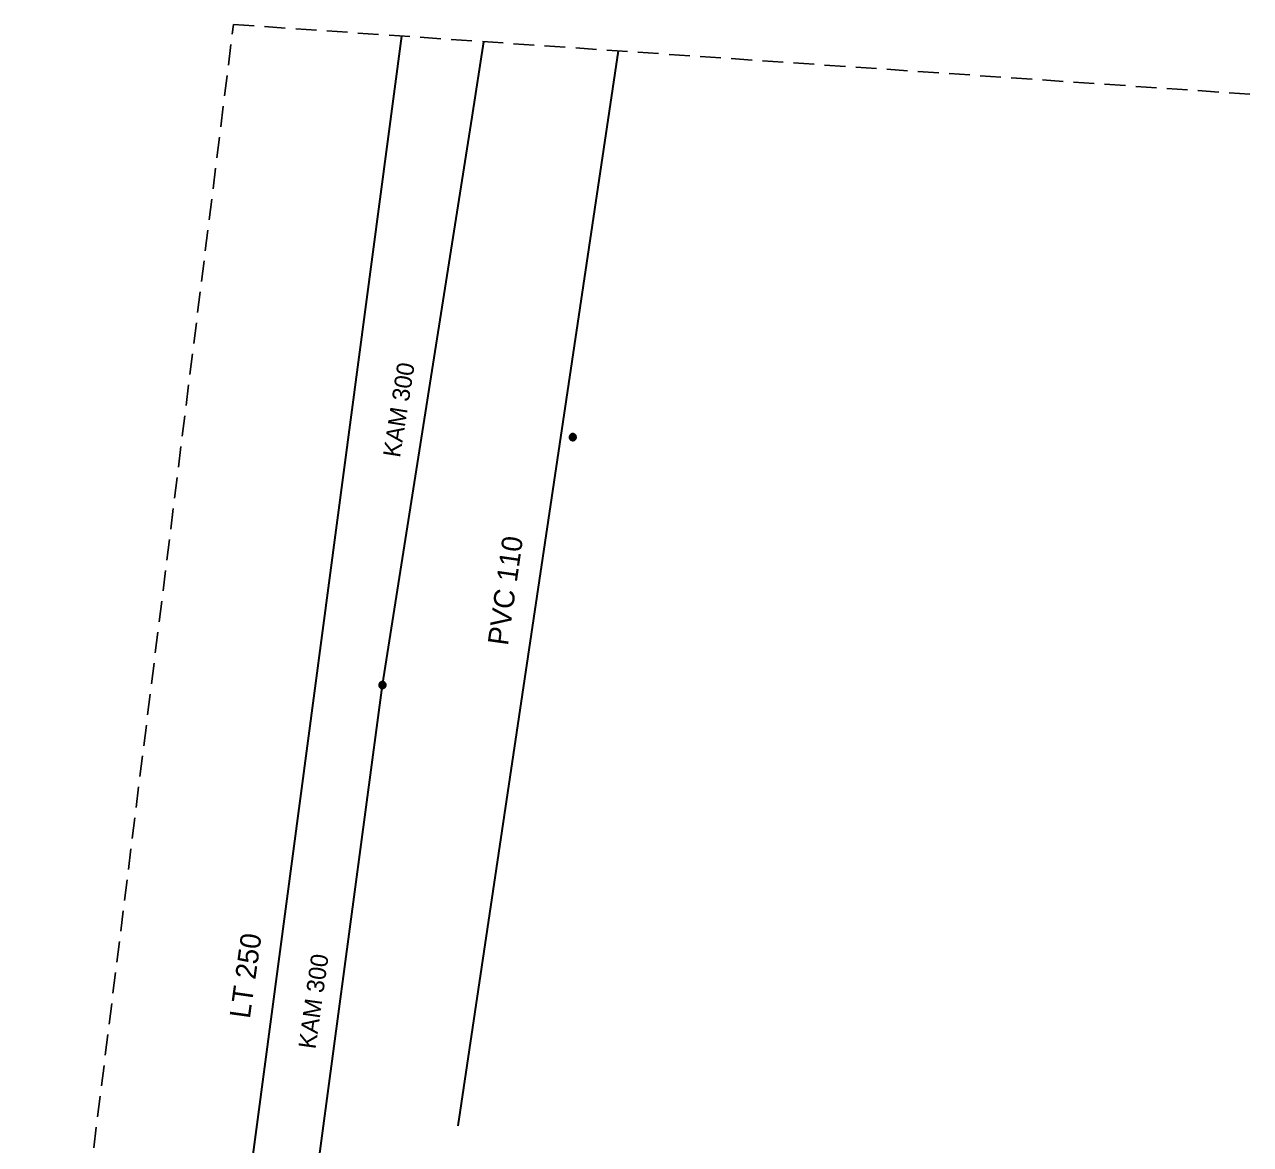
# Model space of a CAD drawing. Extents: x -866761 to -866592, y -1013996 to -1013877.
# Drawn here: x -866760.6 to -866682.7, y -1013947.7 to -1013876.6 of the extents above; entities that cross this region are included whole.
import ezdxf

# ---------------------------------------------------------------- set-up
doc = ezdxf.new("R2010")
doc.units = 0
doc.header["$LTSCALE"] = 0.44
doc.linetypes.add('MEDIUM_DASHED', pattern=[4.5, 3, -1.5])
for name, color, linetype, lineweight in [('1', 7, 'Continuous', 35), ('21', 7, 'Continuous', 35), ('32', 7, 'Continuous', 13), ('62', 7, 'MEDIUM_DASHED', 25), ('8', 7, 'Continuous', 13)]:
    doc.layers.add(name, color=color, linetype=linetype, lineweight=lineweight)

msp = doc.modelspace()

# ---------------------------------------------------------------- linework, layer by layer
at = {"layer": '1'}
msp.add_line((-866722.9, -1013878.242), (-866733.064, -1013946.511), dxfattribs=at)
msp.add_lwpolyline([(-866751.412, -1013984.065), (-866747.177, -1013956.779), (-866736.629, -1013877.301)], dxfattribs=at)
at = {"layer": '21'}
msp.add_line((-866743.067, -1013957.51), (-866737.854, -1013918.522), dxfattribs=at)
msp.add_lwpolyline([(-866737.854, -1013918.522), (-866732.171, -1013882.458), (-866731.425, -1013877.658)], dxfattribs=at)
at = {"layer": '32'}
for points in [[(-866737.623, -1013918.522), (-866737.629, -1013918.47), (-866737.646, -1013918.42), (-866737.675, -1013918.376), (-866737.712, -1013918.339), (-866737.757, -1013918.312), (-866737.807, -1013918.295), (-866737.86, -1013918.291), (-866737.912, -1013918.298), (-866737.961, -1013918.317), (-866738.004, -1013918.346), (-866738.04, -1013918.385), (-866738.066, -1013918.43), (-866738.082, -1013918.481), (-866738.085, -1013918.533), (-866738.077, -1013918.585), (-866738.057, -1013918.634), (-866738.026, -1013918.677), (-866737.987, -1013918.711), (-866737.941, -1013918.737), (-866737.89, -1013918.751), (-866737.837, -1013918.753), (-866737.786, -1013918.743), (-866737.738, -1013918.722), (-866737.695, -1013918.691), (-866737.661, -1013918.65), (-866737.637, -1013918.604), (-866737.625, -1013918.553)], [(-866737.653, -1013918.522), (-866737.659, -1013918.473), (-866737.676, -1013918.427), (-866737.704, -1013918.387), (-866737.741, -1013918.355), (-866737.785, -1013918.333), (-866737.833, -1013918.322), (-866737.882, -1013918.322), (-866737.929, -1013918.335), (-866737.972, -1013918.359), (-866738.008, -1013918.392), (-866738.035, -1013918.433), (-866738.051, -1013918.48), (-866738.055, -1013918.529), (-866738.048, -1013918.577), (-866738.029, -1013918.622), (-866737.999, -1013918.662), (-866737.961, -1013918.693), (-866737.917, -1013918.713), (-866737.869, -1013918.723), (-866737.82, -1013918.721), (-866737.773, -1013918.706), (-866737.73, -1013918.681), (-866737.696, -1013918.647), (-866737.67, -1013918.605), (-866737.656, -1013918.558)], [(-866737.683, -1013918.522), (-866737.689, -1013918.477), (-866737.706, -1013918.435), (-866737.734, -1013918.4), (-866737.77, -1013918.373), (-866737.812, -1013918.356), (-866737.857, -1013918.351), (-866737.902, -1013918.357), (-866737.943, -1013918.376), (-866737.978, -1013918.404), (-866738.005, -1013918.441), (-866738.021, -1013918.483), (-866738.025, -1013918.528), (-866738.018, -1013918.573), (-866737.999, -1013918.614), (-866737.97, -1013918.648), (-866737.933, -1013918.674), (-866737.89, -1013918.69), (-866737.845, -1013918.693), (-866737.8, -1013918.685), (-866737.76, -1013918.665), (-866737.726, -1013918.636), (-866737.7, -1013918.598), (-866737.686, -1013918.555)], [(-866737.713, -1013918.522), (-866737.718, -1013918.481), (-866737.736, -1013918.444), (-866737.763, -1013918.413), (-866737.798, -1013918.392), (-866737.838, -1013918.381), (-866737.879, -1013918.383), (-866737.918, -1013918.396), (-866737.952, -1013918.42), (-866737.977, -1013918.452), (-866737.992, -1013918.49), (-866737.995, -1013918.531), (-866737.987, -1013918.571), (-866737.967, -1013918.607), (-866737.938, -1013918.636), (-866737.901, -1013918.655), (-866737.861, -1013918.663), (-866737.82, -1013918.659), (-866737.782, -1013918.644), (-866737.75, -1013918.618), (-866737.727, -1013918.584), (-866737.714, -1013918.545)], [(-866737.743, -1013918.522), (-866737.748, -1013918.486), (-866737.766, -1013918.454), (-866737.792, -1013918.429), (-866737.826, -1013918.414), (-866737.862, -1013918.411), (-866737.897, -1013918.419), (-866737.928, -1013918.439), (-866737.951, -1013918.467), (-866737.964, -1013918.501), (-866737.964, -1013918.538), (-866737.953, -1013918.573), (-866737.932, -1013918.602), (-866737.902, -1013918.623), (-866737.867, -1013918.633), (-866737.83, -1013918.631), (-866737.796, -1013918.617), (-866737.769, -1013918.594), (-866737.75, -1013918.562), (-866737.743, -1013918.527)], [(-866737.773, -1013918.522), (-866737.778, -1013918.491), (-866737.795, -1013918.465), (-866737.821, -1013918.448), (-866737.851, -1013918.441), (-866737.882, -1013918.445), (-866737.909, -1013918.462), (-866737.927, -1013918.486), (-866737.935, -1013918.517), (-866737.931, -1013918.547), (-866737.916, -1013918.575), (-866737.892, -1013918.594), (-866737.862, -1013918.603), (-866737.831, -1013918.6), (-866737.803, -1013918.586), (-866737.783, -1013918.562), (-866737.773, -1013918.533)], [(-866737.803, -1013918.522), (-866737.808, -1013918.498), (-866737.825, -1013918.48), (-866737.848, -1013918.471), (-866737.872, -1013918.474), (-866737.893, -1013918.488), (-866737.904, -1013918.51), (-866737.904, -1013918.535), (-866737.892, -1013918.556), (-866737.872, -1013918.57), (-866737.847, -1013918.573), (-866737.824, -1013918.564), (-866737.808, -1013918.546)], [(-866737.833, -1013918.522), (-866737.838, -1013918.507), (-866737.853, -1013918.501), (-866737.868, -1013918.505), (-866737.875, -1013918.519), (-866737.871, -1013918.534), (-866737.858, -1013918.543), (-866737.843, -1013918.54), (-866737.833, -1013918.528)]]:
    msp.add_lwpolyline(points, close=True, dxfattribs=at)
at = {"layer": '62'}
msp.add_lwpolyline([(-866747.317, -1013876.568), (-866591.969, -1013887.219), (-866617.09, -1013995.541), (-866760.581, -1013983.282)], close=True, dxfattribs=at)
at = {"layer": '8'}
for points in [[(-866725.544, -1013902.778), (-866725.55, -1013902.726), (-866725.567, -1013902.676), (-866725.596, -1013902.632), (-866725.633, -1013902.595), (-866725.678, -1013902.568), (-866725.728, -1013902.551), (-866725.781, -1013902.547), (-866725.833, -1013902.554), (-866725.882, -1013902.573), (-866725.925, -1013902.602), (-866725.961, -1013902.641), (-866725.987, -1013902.686), (-866726.003, -1013902.737), (-866726.006, -1013902.789), (-866725.998, -1013902.841), (-866725.978, -1013902.89), (-866725.947, -1013902.933), (-866725.908, -1013902.967), (-866725.862, -1013902.993), (-866725.811, -1013903.007), (-866725.758, -1013903.009), (-866725.707, -1013902.999), (-866725.659, -1013902.978), (-866725.616, -1013902.947), (-866725.582, -1013902.906), (-866725.558, -1013902.86), (-866725.546, -1013902.809)], [(-866725.574, -1013902.778), (-866725.58, -1013902.729), (-866725.597, -1013902.683), (-866725.625, -1013902.643), (-866725.662, -1013902.611), (-866725.706, -1013902.589), (-866725.754, -1013902.578), (-866725.803, -1013902.578), (-866725.85, -1013902.591), (-866725.893, -1013902.615), (-866725.929, -1013902.648), (-866725.956, -1013902.689), (-866725.972, -1013902.736), (-866725.976, -1013902.785), (-866725.969, -1013902.833), (-866725.95, -1013902.878), (-866725.92, -1013902.918), (-866725.882, -1013902.949), (-866725.838, -1013902.969), (-866725.79, -1013902.979), (-866725.741, -1013902.977), (-866725.694, -1013902.962), (-866725.651, -1013902.937), (-866725.617, -1013902.903), (-866725.591, -1013902.861), (-866725.577, -1013902.814)], [(-866725.604, -1013902.778), (-866725.61, -1013902.733), (-866725.627, -1013902.691), (-866725.655, -1013902.656), (-866725.691, -1013902.629), (-866725.733, -1013902.612), (-866725.778, -1013902.607), (-866725.823, -1013902.613), (-866725.864, -1013902.632), (-866725.899, -1013902.66), (-866725.926, -1013902.697), (-866725.942, -1013902.739), (-866725.946, -1013902.784), (-866725.939, -1013902.829), (-866725.92, -1013902.87), (-866725.891, -1013902.904), (-866725.854, -1013902.93), (-866725.811, -1013902.946), (-866725.766, -1013902.949), (-866725.721, -1013902.941), (-866725.681, -1013902.921), (-866725.647, -1013902.892), (-866725.621, -1013902.854), (-866725.607, -1013902.811)], [(-866725.634, -1013902.778), (-866725.639, -1013902.737), (-866725.657, -1013902.7), (-866725.684, -1013902.669), (-866725.719, -1013902.648), (-866725.759, -1013902.637), (-866725.8, -1013902.639), (-866725.839, -1013902.652), (-866725.873, -1013902.676), (-866725.898, -1013902.708), (-866725.913, -1013902.746), (-866725.916, -1013902.787), (-866725.908, -1013902.827), (-866725.888, -1013902.863), (-866725.859, -1013902.892), (-866725.822, -1013902.911), (-866725.782, -1013902.919), (-866725.741, -1013902.915), (-866725.703, -1013902.9), (-866725.671, -1013902.874), (-866725.648, -1013902.84), (-866725.635, -1013902.801)], [(-866725.664, -1013902.778), (-866725.669, -1013902.742), (-866725.687, -1013902.71), (-866725.713, -1013902.685), (-866725.747, -1013902.67), (-866725.783, -1013902.667), (-866725.818, -1013902.675), (-866725.849, -1013902.695), (-866725.872, -1013902.723), (-866725.885, -1013902.757), (-866725.885, -1013902.794), (-866725.874, -1013902.829), (-866725.853, -1013902.858), (-866725.823, -1013902.879), (-866725.788, -1013902.889), (-866725.751, -1013902.887), (-866725.717, -1013902.873), (-866725.69, -1013902.85), (-866725.671, -1013902.818), (-866725.664, -1013902.783)], [(-866725.694, -1013902.778), (-866725.699, -1013902.747), (-866725.716, -1013902.721), (-866725.742, -1013902.704), (-866725.772, -1013902.697), (-866725.803, -1013902.701), (-866725.83, -1013902.718), (-866725.848, -1013902.742), (-866725.856, -1013902.773), (-866725.852, -1013902.803), (-866725.837, -1013902.831), (-866725.813, -1013902.85), (-866725.783, -1013902.859), (-866725.752, -1013902.856), (-866725.724, -1013902.842), (-866725.704, -1013902.818), (-866725.694, -1013902.789)], [(-866725.724, -1013902.778), (-866725.729, -1013902.754), (-866725.746, -1013902.736), (-866725.769, -1013902.727), (-866725.793, -1013902.73), (-866725.814, -1013902.744), (-866725.825, -1013902.766), (-866725.825, -1013902.791), (-866725.813, -1013902.812), (-866725.793, -1013902.826), (-866725.768, -1013902.829), (-866725.745, -1013902.82), (-866725.729, -1013902.802)], [(-866725.754, -1013902.778), (-866725.759, -1013902.763), (-866725.774, -1013902.757), (-866725.789, -1013902.761), (-866725.796, -1013902.775), (-866725.792, -1013902.79), (-866725.779, -1013902.799), (-866725.764, -1013902.796), (-866725.754, -1013902.784)]]:
    msp.add_lwpolyline(points, close=True, dxfattribs=at)

# ---------------------------------------------------------------- texts
at = {"layer": '1'}
for s, height, rotation, p in [('KAM 300 ', 1.1, 81, (-866736.747, -1013904.114)), ('PVC 110 ', 1.3, 82, (-866729.895, -1013916.055)), ('LT 250', 1.3, 82, (-866746.279, -1013939.747)), ('KAM 300 ', 1.1, 82, (-866742.111, -1013941.679))]:
    msp.add_text(s, height=height, rotation=rotation, dxfattribs=at).set_placement(p)

doc.saveas('drawing.dxf')
